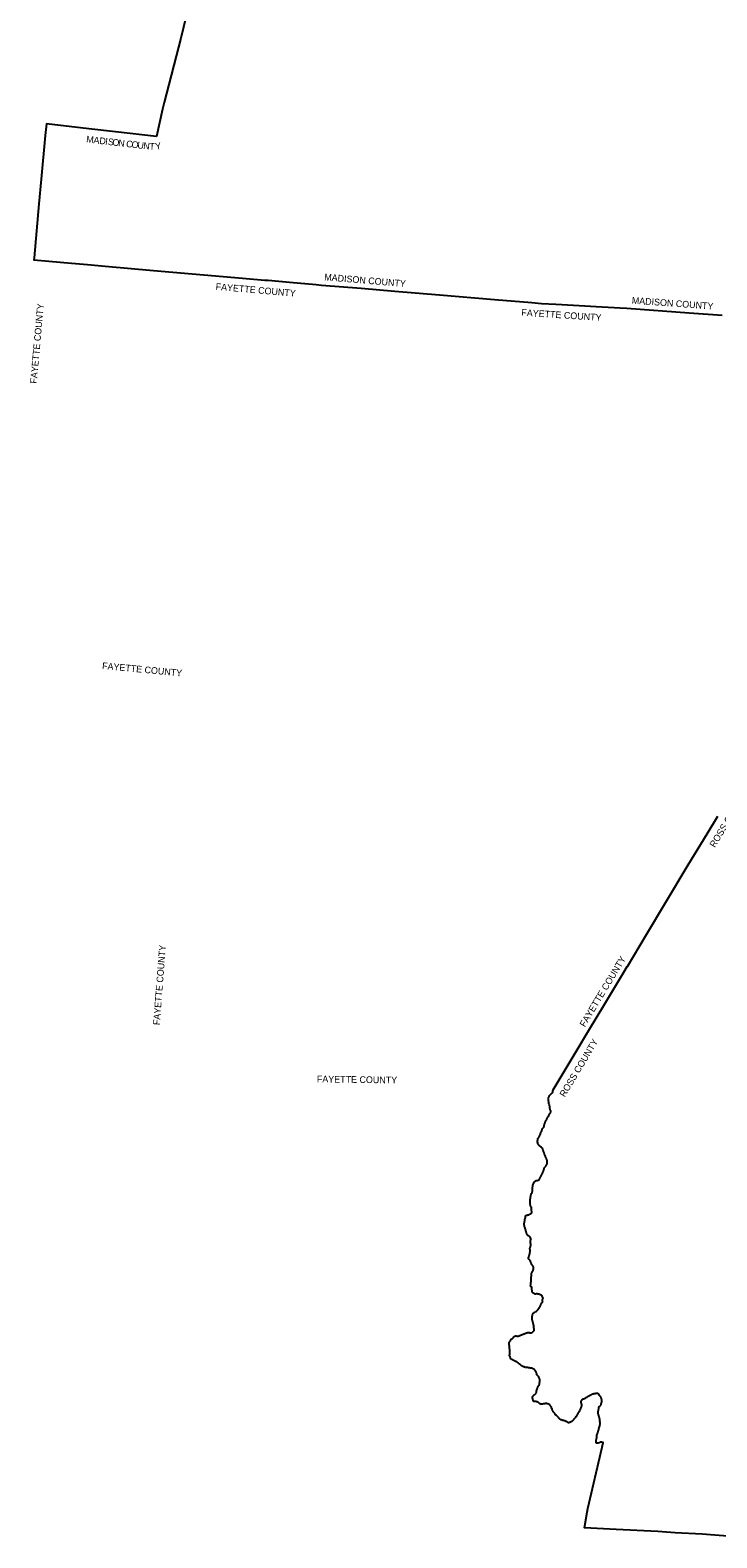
# Model space of a CAD drawing. Extents: x 1643459 to 2064572, y 425441 to 780708.
# Drawn here: x 1643459 to 1746483, y 435826 to 661772 of the extents above; entities that cross this region are included whole.
import ezdxf

# ---------------------------------------------------------------- set-up
doc = ezdxf.new("R2010")
doc.units = 0
doc.layers.add('GM_X_Minor_River', color=7, linetype='Continuous')
doc.layers.add('GM_X_Township_Subdivision', color=7, linetype='Continuous')

msp = doc.modelspace()

# ---------------------------------------------------------------- linework, layer by layer
at = {"layer": 'GM_X_Minor_River'}
for points in [[(1666885, 663874), (1666084, 660564), (1663561, 650929), (1663296, 649933), (1662403, 645855), (1656287, 646528), (1652288, 647008), (1645905, 647740), (1645710, 645966), (1645124, 639449), (1644788, 635767), (1644047, 627642), (1644023, 627376), (1646278, 627176), (1649675, 626876), (1652057, 626672), (1654722, 626423), (1661976, 625747), (1675318, 624618), (1678685, 624323), (1679159, 624282), (1682349, 624003), (1686356, 623652), (1687189, 623580), (1693117, 623083), (1698190, 622658), (1704859, 622098), (1713144, 621404), (1718727, 620944), (1720196, 620823), (1722331, 620688), (1724957, 620538), (1728386, 620349), (1731998, 620173), (1732995, 620100), (1742304, 619412), (1747296, 619048)], [(1751291, 435826), (1744285, 436361), (1740249, 436602), (1739572, 436632), (1737649, 436770), (1731391, 437070), (1726608, 437330), (1727045, 439667), (1727145, 440204), (1729274, 449424), (1729434, 450116), (1729392, 450119), (1729326, 450126), (1729262, 450139), (1729207, 450146), (1729153, 450151), (1729099, 450160), (1729039, 450143), (1728985, 450143), (1728926, 450106), (1728864, 450075), (1728809, 450054), (1728755, 450050), (1728701, 450031), (1728639, 450018), (1728585, 450009), (1728511, 449998), (1728456, 449993), (1728403, 450017), (1728396, 450070), (1728391, 450128), (1728377, 450180), (1728368, 450241), (1728369, 450297), (1728362, 450351), (1728373, 450441), (1728397, 450519), (1728417, 450577), (1728430, 450633), (1728443, 450691), (1728452, 450745), (1728457, 450803), (1728470, 450873), (1728481, 450939), (1728484, 451003), (1728485, 451069), (1728492, 451127), (1728493, 451177), (1728498, 451231), (1728515, 451299), (1728534, 451359), (1728554, 451421), (1728576, 451493), (1728602, 451548), (1728619, 451612), (1728640, 451670), (1728653, 451726), (1728678, 451778), (1728693, 451830), (1728716, 451906), (1728743, 451971), (1728756, 452031), (1728767, 452093), (1728780, 452151), (1728799, 452209), (1728819, 452267), (1728845, 452383), (1728874, 452445), (1728914, 452534), (1728925, 452598), (1728930, 452668), (1728936, 452719), (1728959, 452778), (1728948, 452833), (1728961, 452915), (1728960, 452967), (1728959, 453033), (1728950, 453103), (1728949, 453153), (1728948, 453228), (1728953, 453290), (1728948, 453352), (1728945, 453402), (1728940, 453460), (1728935, 453521), (1728936, 453589), (1728909, 453641), (1728898, 453710), (1728886, 453762), (1728870, 453852), (1728845, 453915), (1728832, 453967), (1728816, 454017), (1728799, 454070), (1728780, 454120), (1728761, 454175), (1728740, 454239), (1728723, 454300), (1728716, 454354), (1728697, 454418), (1728689, 454470), (1728671, 454583), (1728666, 454643), (1728667, 454719), (1728680, 454771), (1728689, 454827), (1728700, 454879), (1728713, 454931), (1728727, 454993), (1728732, 455043), (1728751, 455105), (1728752, 455155), (1728751, 455205), (1728758, 455265), (1728762, 455319), (1728772, 455387), (1728802, 455439), (1728847, 455505), (1728912, 455568), (1728979, 455603), (1729044, 455652), (1729090, 455710), (1729109, 455766), (1729126, 455819), (1729143, 455883), (1729148, 455935), (1729171, 456009), (1729192, 456075), (1729205, 456135), (1729218, 456189), (1729215, 456249), (1729210, 456313), (1729224, 456365), (1729237, 456429), (1729223, 456515), (1729209, 456566), (1729194, 456618), (1729159, 456733), (1729133, 456790), (1729100, 456847), (1729058, 456911), (1729031, 456961), (1729005, 457014), (1728972, 457067), (1728928, 457129), (1728889, 457180), (1728841, 457239), (1728793, 457297), (1728752, 457354), (1728690, 457410), (1728639, 457453), (1728585, 457465), (1728533, 457464), (1728479, 457466), (1728367, 457453), (1728303, 457438), (1728236, 457420), (1728178, 457420), (1728114, 457419), (1728056, 457409), (1728001, 457388), (1727943, 457370), (1727882, 457352), (1727828, 457335), (1727767, 457311), (1727714, 457286), (1727658, 457265), (1727603, 457239), (1727550, 457214), (1727489, 457174), (1727433, 457151), (1727380, 457118), (1727315, 457086), (1727254, 457056), (1727195, 457021), (1727126, 456987), (1727073, 456940), (1727022, 456912), (1726967, 456873), (1726900, 456835), (1726843, 456802), (1726774, 456762), (1726717, 456727), (1726664, 456697), (1726614, 456668), (1726561, 456637), (1726510, 456611), (1726454, 456592), (1726393, 456586), (1726343, 456577), (1726288, 456538), (1726225, 456506), (1726209, 456455), (1726164, 456402), (1726123, 456348), (1726090, 456292), (1726071, 456238), (1726071, 456186), (1726080, 456134), (1726087, 456084), (1726110, 456027), (1726125, 455947), (1726134, 455893), (1726155, 455834), (1726166, 455782), (1726176, 455726), (1726185, 455657), (1726174, 455603), (1726159, 455548), (1726138, 455488), (1726113, 455436), (1726078, 455376), (1726063, 455320), (1726036, 455245), (1726019, 455173), (1725990, 455113), (1725971, 455061), (1725955, 455009), (1725924, 454957), (1725893, 454902), (1725872, 454842), (1725837, 454784), (1725784, 454723), (1725759, 454671), (1725722, 454601), (1725682, 454546), (1725641, 454492), (1725630, 454432), (1725575, 454379), (1725558, 454321), (1725525, 454267), (1725497, 454216), (1725469, 454146), (1725429, 454090), (1725382, 454035), (1725351, 453979), (1725292, 453922), (1725259, 453868), (1725212, 453813), (1725157, 453747), (1725117, 453696), (1725056, 453643), (1724997, 453567), (1724952, 453514), (1724905, 453452), (1724862, 453397), (1724808, 453362), (1724763, 453306), (1724708, 453273), (1724645, 453222), (1724579, 453194), (1724523, 453159), (1724458, 453138), (1724406, 453111), (1724344, 453108), (1724293, 453074), (1724237, 453081), (1724174, 453096), (1724118, 453115), (1724064, 453144), (1724005, 453183), (1723954, 453211), (1723896, 453244), (1723842, 453263), (1723785, 453292), (1723720, 453339), (1723662, 453368), (1723610, 453375), (1723556, 453386), (1723497, 453405), (1723445, 453415), (1723381, 453428), (1723327, 453445), (1723268, 453460), (1723202, 453477), (1723150, 453498), (1723087, 453523), (1723031, 453548), (1722972, 453585), (1722918, 453621), (1722867, 453658), (1722822, 453709), (1722788, 453764), (1722761, 453826), (1722700, 453871), (1722669, 453924), (1722617, 453948), (1722564, 454007), (1722515, 454062), (1722452, 454109), (1722405, 454162), (1722345, 454205), (1722286, 454274), (1722239, 454339), (1722202, 454394), (1722161, 454446), (1722110, 454495), (1722063, 454564), (1722026, 454617), (1721979, 454677), (1721934, 454734), (1721906, 454787), (1721872, 454859), (1721846, 454912), (1721829, 454970), (1721810, 455021), (1721791, 455079), (1721784, 455131), (1721755, 455182), (1721723, 455234), (1721698, 455289), (1721683, 455343), (1721672, 455396), (1721625, 455458), (1721594, 455521), (1721559, 455572), (1721527, 455622), (1721492, 455673), (1721451, 455724), (1721400, 455768), (1721346, 455805), (1721293, 455838), (1721239, 455867), (1721186, 455894), (1721130, 455913), (1721074, 455926), (1721022, 455934), (1720969, 455947), (1720901, 455962), (1720837, 455957), (1720759, 455958), (1720708, 455953), (1720657, 455932), (1720607, 455924), (1720547, 455893), (1720497, 455890), (1720445, 455893), (1720395, 455883), (1720343, 455874), (1720292, 455867), (1720229, 455866), (1720175, 455870), (1720111, 455875), (1720057, 455882), (1719997, 455905), (1719941, 455924), (1719876, 455965), (1719821, 456016), (1719770, 456061), (1719710, 456096), (1719659, 456133), (1719603, 456169), (1719547, 456186), (1719480, 456219), (1719428, 456230), (1719370, 456243), (1719318, 456248), (1719266, 456250), (1719211, 456257), (1719153, 456254), (1719085, 456259), (1719025, 456274), (1718968, 456329), (1718923, 456386), (1718915, 456436), (1718910, 456490), (1718886, 456548), (1718859, 456607), (1718854, 456657), (1718827, 456708), (1718822, 456766), (1718817, 456822), (1718820, 456876), (1718833, 456932), (1718850, 456986), (1718879, 457041), (1718936, 457098), (1718977, 457158), (1719028, 457193), (1719077, 457244), (1719131, 457285), (1719184, 457330), (1719245, 457377), (1719296, 457422), (1719351, 457485), (1719394, 457547), (1719411, 457613), (1719424, 457674), (1719427, 457728), (1719443, 457788), (1719436, 457853), (1719463, 457940), (1719476, 457994), (1719496, 458054), (1719527, 458107), (1719538, 458175), (1719559, 458239), (1719578, 458301), (1719601, 458357), (1719622, 458418), (1719645, 458472), (1719696, 458531), (1719737, 458588), (1719789, 458646), (1719826, 458705), (1719847, 458759), (1719864, 458823), (1719883, 458874), (1719890, 458934), (1719893, 458988), (1719894, 459040), (1719897, 459092), (1719902, 459155), (1719909, 459225), (1719915, 459325), (1719920, 459385), (1719917, 459437), (1719911, 459501), (1719906, 459553), (1719899, 459608), (1719886, 459658), (1719869, 459712), (1719840, 459763), (1719815, 459822), (1719780, 459874), (1719749, 459939), (1719716, 459990), (1719679, 460045), (1719614, 460098), (1719563, 460157), (1719528, 460216), (1719497, 460267), (1719488, 460327), (1719467, 460381), (1719452, 460434), (1719445, 460492), (1719417, 460559), (1719398, 460611), (1719381, 460662), (1719344, 460724), (1719311, 460775), (1719274, 460836), (1719237, 460893), (1719194, 460948), (1719155, 460999), (1719100, 461052), (1719049, 461089), (1718990, 461130), (1718939, 461177), (1718885, 461206), (1718826, 461223), (1718774, 461228), (1718718, 461231), (1718664, 461259), (1718607, 461272), (1718549, 461279), (1718485, 461270), (1718425, 461283), (1718363, 461286), (1718309, 461297), (1718251, 461304), (1718186, 461324), (1718130, 461331), (1718074, 461340), (1718009, 461363), (1717951, 461364), (1717897, 461371), (1717839, 461380), (1717779, 461378), (1717717, 461391), (1717658, 461400), (1717606, 461417), (1717548, 461432), (1717491, 461451), (1717423, 461485), (1717360, 461514), (1717298, 461547), (1717245, 461580), (1717194, 461619), (1717141, 461662), (1717078, 461718), (1717017, 461765), (1716950, 461814), (1716897, 461857), (1716841, 461901), (1716778, 461946), (1716725, 461987), (1716672, 462022), (1716618, 462055), (1716567, 462096), (1716514, 462131), (1716457, 462172), (1716400, 462216), (1716348, 462239), (1716287, 462264), (1716221, 462301), (1716170, 462324), (1716108, 462349), (1716049, 462385), (1715991, 462410), (1715930, 462441), (1715873, 462480), (1715805, 462511), (1715746, 462539), (1715693, 462576), (1715640, 462621), (1715573, 462678), (1715544, 462733), (1715527, 462791), (1715500, 462842), (1715471, 462899), (1715452, 462957), (1715425, 463012), (1715406, 463072), (1715379, 463133), (1715390, 463191), (1715397, 463230), (1715402, 463255), (1715413, 463307), (1715420, 463359), (1715425, 463421), (1715432, 463477), (1715434, 463577), (1715439, 463627), (1715442, 463693), (1715439, 463761), (1715438, 463819), (1715424, 463936), (1715403, 463986), (1715405, 464048), (1715400, 464101), (1715391, 464163), (1715386, 464213), (1715385, 464263), (1715380, 464313), (1715376, 464364), (1715373, 464416), (1715371, 464474), (1715362, 464542), (1715357, 464600), (1715350, 464663), (1715343, 464715), (1715334, 464773), (1715321, 464830), (1715314, 464884), (1715311, 464948), (1715313, 465008), (1715328, 465066), (1715351, 465128), (1715396, 465189), (1715439, 465240), (1715470, 465302), (1715499, 465355), (1715526, 465421), (1715563, 465484), (1715647, 465583), (1715702, 465632), (1715759, 465673), (1715818, 465716), (1715868, 465763), (1715926, 465822), (1715982, 465871), (1716041, 465928), (1716086, 465979), (1716147, 466030), (1716202, 466067), (1716266, 466092), (1716318, 466095), (1716370, 466096), (1716428, 466079), (1716480, 466060), (1716537, 466047), (1716593, 466040), (1716651, 466051), (1716712, 466062), (1716778, 466091), (1716834, 466105), (1716885, 466123), (1716935, 466156), (1716991, 466165), (1717042, 466202), (1717167, 466235), (1717257, 466284), (1717312, 466309), (1717370, 466330), (1717429, 466357), (1717485, 466372), (1717539, 466397), (1717590, 466416), (1717654, 466433), (1717706, 466450), (1717773, 466478), (1717823, 466502), (1717874, 466523), (1717926, 466546), (1717990, 466567), (1718049, 466577), (1718111, 466586), (1718163, 466593), (1718217, 466590), (1718279, 466585), (1718332, 466582), (1718400, 466569), (1718458, 466562), (1718518, 466561), (1718600, 466563), (1718658, 466570), (1718708, 466587), (1718767, 466614), (1718837, 466649), (1718894, 466692), (1718945, 466735), (1718998, 466786), (1719015, 466838), (1719052, 466891), (1719067, 466953), (1719070, 467015), (1719069, 467073), (1719060, 467135), (1719055, 467186), (1719043, 467248), (1719036, 467298), (1719029, 467360), (1719024, 467415), (1719023, 467481), (1719020, 467541), (1719015, 467601), (1719015, 467671), (1718997, 467724), (1718987, 467778), (1718971, 467829), (1718955, 467901), (1718936, 467959), (1718919, 468026), (1718906, 468078), (1718883, 468143), (1718864, 468195), (1718851, 468248), (1718840, 468306), (1718814, 468411), (1718805, 468461), (1718796, 468513), (1718791, 468569), (1718786, 468624), (1718786, 468686), (1718787, 468748), (1718780, 468820), (1718779, 468878), (1718778, 468940), (1718779, 468996), (1718789, 469058), (1718804, 469112), (1718809, 469168), (1718836, 469236), (1718843, 469294), (1718858, 469348), (1718887, 469399), (1718918, 469457), (1718945, 469508), (1719006, 469553), (1719057, 469610), (1719111, 469635), (1719162, 469668), (1719214, 469700), (1719267, 469731), (1719323, 469770), (1719404, 469822), (1719463, 469867), (1719518, 469910), (1719577, 469963), (1719628, 469998), (1719685, 470059), (1719734, 470136), (1719783, 470200), (1719826, 470253), (1719867, 470322), (1719900, 470382), (1719931, 470433), (1719961, 470495), (1719984, 470553), (1720011, 470618), (1720022, 470690), (1720055, 470741), (1720080, 470799), (1720115, 470851), (1720148, 470904), (1720181, 470959), (1720228, 471025), (1720263, 471076), (1720310, 471131), (1720329, 471183), (1720348, 471239), (1720353, 471299), (1720348, 471365), (1720337, 471417), (1720340, 471475), (1720343, 471525), (1720356, 471577), (1720377, 471629), (1720398, 471687), (1720427, 471742), (1720398, 471801), (1720349, 471856), (1720311, 471923), (1720294, 471979), (1720281, 472029), (1720262, 472082), (1720217, 472135), (1720163, 472178), (1720110, 472203), (1720044, 472226), (1719979, 472253), (1719927, 472276), (1719870, 472308), (1719816, 472329), (1719759, 472346), (1719699, 472355), (1719629, 472366), (1719567, 472379), (1719504, 472395), (1719448, 472388), (1719397, 472375), (1719335, 472364), (1719285, 472355), (1719229, 472360), (1719167, 472371), (1719104, 472396), (1719050, 472415), (1718999, 472430), (1718938, 472489), (1718889, 472546), (1718842, 472597), (1718801, 472650), (1718784, 472701), (1718771, 472755), (1718762, 472815), (1718755, 472869), (1718754, 472952), (1718747, 473010), (1718742, 473060), (1718737, 473120), (1718734, 473170), (1718731, 473222), (1718724, 473275), (1718715, 473331), (1718708, 473383), (1718649, 473422), (1718597, 473465), (1718570, 473518), (1718554, 473578), (1718547, 473638), (1718546, 473688), (1718555, 473746), (1718557, 473798), (1718565, 473856), (1718573, 473910), (1718583, 473978), (1718586, 474040), (1718597, 474092), (1718602, 474148), (1718605, 474214), (1718608, 474294), (1718611, 474354), (1718611, 474420), (1718615, 474474), (1718619, 474548), (1718624, 474608), (1718623, 474662), (1718622, 474716), (1718631, 474768), (1718630, 474824), (1718641, 474878), (1718648, 474934), (1718659, 474990), (1718658, 475052), (1718669, 475127), (1718664, 475178), (1718669, 475230), (1718676, 475299), (1718681, 475355), (1718695, 475475), (1718704, 475535), (1718729, 475603), (1718776, 475666), (1718801, 475717), (1718846, 475779), (1718887, 475830), (1718922, 475881), (1718937, 475937), (1718946, 475991), (1718949, 476043), (1718954, 476103), (1718959, 476169), (1718960, 476239), (1718965, 476292), (1718966, 476358), (1718959, 476419), (1718938, 476483), (1718905, 476540), (1718858, 476597), (1718813, 476651), (1718776, 476704), (1718733, 476759), (1718700, 476814), (1718677, 476870), (1718656, 476928), (1718647, 476983), (1718608, 477043), (1718589, 477108), (1718562, 477158), (1718539, 477217), (1718514, 477267), (1718485, 477320), (1718450, 477376), (1718413, 477429), (1718361, 477478), (1718300, 477529), (1718267, 477580), (1718232, 477630), (1718209, 477683), (1718200, 477741), (1718209, 477793), (1718242, 477858), (1718267, 477910), (1718284, 477969), (1718303, 478021), (1718326, 478081), (1718342, 478132), (1718357, 478190), (1718382, 478254), (1718395, 478313), (1718404, 478369), (1718411, 478421), (1718428, 478487), (1718429, 478539), (1718440, 478590), (1718449, 478644), (1718462, 478704), (1718457, 478760), (1718464, 478818), (1718457, 478882), (1718454, 478940), (1718453, 478992), (1718450, 479046), (1718438, 479096), (1718429, 479147), (1718426, 479207), (1718439, 479258), (1718458, 479310), (1718485, 479361), (1718500, 479413), (1718525, 479475), (1718548, 479526), (1718562, 479578), (1718583, 479638), (1718594, 479699), (1718591, 479749), (1718590, 479799), (1718569, 479852), (1718554, 479904), (1718535, 479972), (1718520, 480033), (1718505, 480097), (1718502, 480149), (1718503, 480209), (1718510, 480261), (1718527, 480315), (1718546, 480380), (1718559, 480436), (1718574, 480492), (1718593, 480547), (1718604, 480601), (1718569, 480656), (1718524, 480719), (1718507, 480781), (1718480, 480831), (1718449, 480886), (1718411, 480937), (1718370, 480992), (1718313, 481045), (1718252, 481066), (1718184, 481093), (1718125, 481130), (1718070, 481185), (1718035, 481242), (1718012, 481300), (1717987, 481361), (1717964, 481413), (1717941, 481474), (1717924, 481532), (1717911, 481584), (1717896, 481637), (1717883, 481693), (1717868, 481749), (1717845, 481812), (1717840, 481847), (1717836, 481874), (1717819, 481928), (1717808, 481985), (1717793, 482035), (1717780, 482089), (1717737, 482178), (1717714, 482230), (1717699, 482283), (1717674, 482333), (1717653, 482390), (1717638, 482444), (1717631, 482496), (1717621, 482596), (1717607, 482647), (1717598, 482701), (1717591, 482753), (1717585, 482853), (1717588, 482911), (1717593, 482961), (1717602, 483023), (1717609, 483087), (1717620, 483147), (1717629, 483201), (1717642, 483255), (1717653, 483308), (1717662, 483366), (1717669, 483424), (1717670, 483486), (1717698, 483566), (1717711, 483622), (1717726, 483687), (1717756, 483791), (1717769, 483857), (1717778, 483909), (1717775, 483959), (1717764, 484019), (1717793, 484071), (1717824, 484124), (1717876, 484141), (1717926, 484166), (1717978, 484177), (1718037, 484194), (1718095, 484205), (1718145, 484216), (1718195, 484225), (1718259, 484250), (1718320, 484291), (1718379, 484314), (1718429, 484343), (1718481, 484364), (1718538, 484397), (1718590, 484422), (1718643, 484453), (1718686, 484508), (1718727, 484563), (1718746, 484629), (1718745, 484687), (1718736, 484747), (1718711, 484800), (1718694, 484850), (1718675, 484909), (1718666, 484973), (1718665, 485023), (1718666, 485073), (1718669, 485125), (1718674, 485179), (1718675, 485233), (1718672, 485283), (1718649, 485338), (1718616, 485393), (1718569, 485450), (1718550, 485518), (1718535, 485568), (1718522, 485633), (1718505, 485683), (1718500, 485741), (1718494, 485798), (1718486, 485848), (1718477, 485904), (1718472, 485954), (1718470, 486014), (1718470, 486066), (1718470, 486125), (1718467, 486183), (1718476, 486235), (1718477, 486287), (1718486, 486345), (1718485, 486409), (1718486, 486463), (1718495, 486529), (1718498, 486585), (1718513, 486639), (1718508, 486691), (1718513, 486755), (1718528, 486811), (1718527, 486861), (1718544, 486923), (1718553, 486986), (1718556, 487045), (1718564, 487121), (1718581, 487174), (1718600, 487234), (1718613, 487286), (1718638, 487348), (1718681, 487411), (1718712, 487468), (1718751, 487526), (1718766, 487580), (1718779, 487633), (1718792, 487689), (1718805, 487745), (1718816, 487797), (1718815, 487849), (1718818, 487971), (1718813, 488031), (1718822, 488089), (1718827, 488157), (1718836, 488209), (1718843, 488267), (1718846, 488325), (1718847, 488377), (1718852, 488429), (1718859, 488483), (1718860, 488540), (1718873, 488599), (1718888, 488651), (1718897, 488703), (1718920, 488761), (1718929, 488821), (1718944, 488881), (1718969, 488936), (1719000, 488990), (1719024, 489049), (1719059, 489105), (1719109, 489154), (1719154, 489205), (1719201, 489265), (1719252, 489306), (1719307, 489333), (1719365, 489358), (1719423, 489358), (1719477, 489359), (1719532, 489388), (1719592, 489401), (1719642, 489412), (1719704, 489439), (1719759, 489456), (1719813, 489493), (1719858, 489545), (1719891, 489598), (1719918, 489656), (1719937, 489707), (1719962, 489767), (1719982, 489825), (1720011, 489884), (1720048, 489942), (1720075, 489993), (1720106, 490045), (1720139, 490102), (1720182, 490154), (1720201, 490213), (1720236, 490275), (1720261, 490335), (1720282, 490396), (1720317, 490450), (1720332, 490508), (1720361, 490567), (1720380, 490623), (1720409, 490678), (1720440, 490736), (1720463, 490796), (1720486, 490851), (1720504, 490915), (1720521, 490967), (1720542, 491029), (1720557, 491088), (1720568, 491142), (1720589, 491206), (1720614, 491258), (1720643, 491315), (1720678, 491367), (1720725, 491420), (1720768, 491485), (1720811, 491541), (1720850, 491600), (1720894, 491663), (1720927, 491717), (1720966, 491772), (1720981, 491832), (1721004, 491886), (1721009, 491938), (1721018, 491998), (1721025, 492060), (1721030, 492110), (1721035, 492162), (1721038, 492230), (1721031, 492280), (1721018, 492334), (1721011, 492403), (1720994, 492459), (1720970, 492524), (1720947, 492574), (1720928, 492627), (1720901, 492677), (1720876, 492728), (1720853, 492778), (1720830, 492839), (1720791, 492900), (1720778, 492952), (1720759, 493009), (1720728, 493063), (1720703, 493118), (1720670, 493183), (1720659, 493237), (1720644, 493297), (1720629, 493352), (1720601, 493408), (1720580, 493461), (1720561, 493527), (1720536, 493578), (1720525, 493630), (1720498, 493683), (1720483, 493749), (1720462, 493806), (1720443, 493858), (1720423, 493928), (1720405, 493975), (1720388, 494032), (1720366, 494098), (1720343, 494155), (1720316, 494210), (1720289, 494233), (1720242, 494283), (1720195, 494334), (1720121, 494403), (1719981, 494509), (1719818, 494642), (1719762, 494711), (1719690, 494817), (1719621, 494948), (1719607, 495031), (1719589, 495150), (1719592, 495253), (1719609, 495522), (1719639, 495620), (1719685, 495719), (1719720, 495780), (1719779, 495837), (1719814, 495895), (1719845, 495946), (1719866, 496000), (1719891, 496053), (1719920, 496105), (1719943, 496165), (1719968, 496222), (1719979, 496284), (1720010, 496338), (1720023, 496398), (1720042, 496453), (1720075, 496511), (1720088, 496563), (1720103, 496619), (1720126, 496672), (1720155, 496726), (1720182, 496781), (1720207, 496835), (1720224, 496897), (1720249, 496955), (1720262, 497008), (1720273, 497060), (1720294, 497116), (1720335, 497169), (1720380, 497223), (1720437, 497268), (1720486, 497325), (1720517, 497376), (1720544, 497430), (1720557, 497484), (1720566, 497546), (1720583, 497606), (1720594, 497658), (1720605, 497711), (1720621, 497767), (1720625, 497817), (1720646, 497871), (1720663, 497925), (1720678, 497977), (1720703, 498030), (1720714, 498082), (1720727, 498136), (1720750, 498194), (1720774, 498249), (1720799, 498303), (1720819, 498355), (1720871, 498412), (1720919, 498463), (1720955, 498528), (1720980, 498580), (1721007, 498646), (1721034, 498713), (1721063, 498767), (1721094, 498822), (1721113, 498880), (1721140, 498940), (1721166, 498995), (1721250, 499117), (1721283, 499178), (1721335, 499237), (1721371, 499300), (1721386, 499352), (1721426, 499413), (1721455, 499464), (1721505, 499521), (1721530, 499576), (1721550, 499634), (1721555, 499690), (1721555, 499744), (1721550, 499796), (1721524, 499851), (1721503, 499904), (1721484, 499959), (1721470, 500017), (1721463, 500067), (1721461, 500118), (1721442, 500172), (1721428, 500223), (1721425, 500279), (1721427, 500337), (1721430, 500391), (1721432, 500449), (1721420, 500522), (1721398, 500585), (1721383, 500647), (1721375, 500710), (1721356, 500762), (1721334, 500813), (1721293, 500868), (1721281, 500921), (1721274, 500975), (1721270, 501031), (1721255, 501084), (1721255, 501158), (1721257, 501216), (1721244, 501270), (1721238, 501335), (1721236, 501389), (1721225, 501443), (1721227, 501500), (1721204, 501550), (1721197, 501601), (1721203, 501665), (1721206, 501715), (1721220, 501768), (1721245, 501822), (1721265, 501875), (1721300, 501939), (1721320, 501992), (1721340, 502043), (1721385, 502098), (1721434, 502152), (1721482, 502203), (1721527, 502254), (1721574, 502307), (1721622, 502364), (1721675, 502411), (1721726, 502449), (1721783, 502498), (1721834, 502539), (1721875, 502598), (1721883, 502652), (1721884, 502706), (1721877, 502756), (1721844, 502834), (1721935, 502985), (1725220, 508449), (1727396, 512075), (1729526, 515601), (1732534, 520603), (1733029, 521426), (1733056, 521470), (1735942, 526252), (1738830, 531095), (1742194, 536665), (1745018, 541341), (1746626, 544003)]]:
    msp.add_lwpolyline(points, dxfattribs=at)

# ---------------------------------------------------------------- texts
at = {"layer": 'GM_X_Township_Subdivision'}
for s, rotation, p in [('M', 353.18004, (1651838, 644958)), ('A', 353.46648, (1652923, 644828)), ('D', 353.49583, (1653802, 644727)), ('I', 353.50027, (1654681, 644627)), ('S', 353.49861, (1655087, 644581)), ('O', 353.50008, (1655760, 644504)), ('N', 353.49867, (1656639, 644404)), ('C', 353.49997, (1657820, 644269)), ('O', 353.49977, (1658628, 644177)), ('U', 353.49867, (1659507, 644077)), ('N', 353.74492, (1660390, 643976)), ('T', 356.26609, (1661317, 643876)), ('Y', 9.82319, (1662321, 643841)), ('FAYETTE COUNTY', 355.06254, (1671264, 622863)), ('MADISON COUNTY', 355.20433, (1687556, 624297)), ('MADISON COUNTY', 355.79634, (1733696, 620795)), ('FAYETTE COUNTY', 84.82452, (1644445, 608769)), ('FAYETTE COUNTY', 356.29765, (1717130, 618977)), ('FAYETTE COUNTY', 354.61377, (1654224, 566044)), ('ROSS COUNTY', 58.75529, (1746171, 539194)), ('FAYETTE COUNTY', 85.57272, (1662901, 512631)), ('FAYETTE COUNTY', 58.96435, (1726676, 512295)), ('ROSS COUNTY', 59.00484, (1723668, 501797)), ('FAYETTE COUNTY', 359.1852, (1686471, 504095))]:
    msp.add_text(s, height=1000, rotation=rotation, dxfattribs=at).set_placement(p)

doc.saveas('drawing.dxf')
